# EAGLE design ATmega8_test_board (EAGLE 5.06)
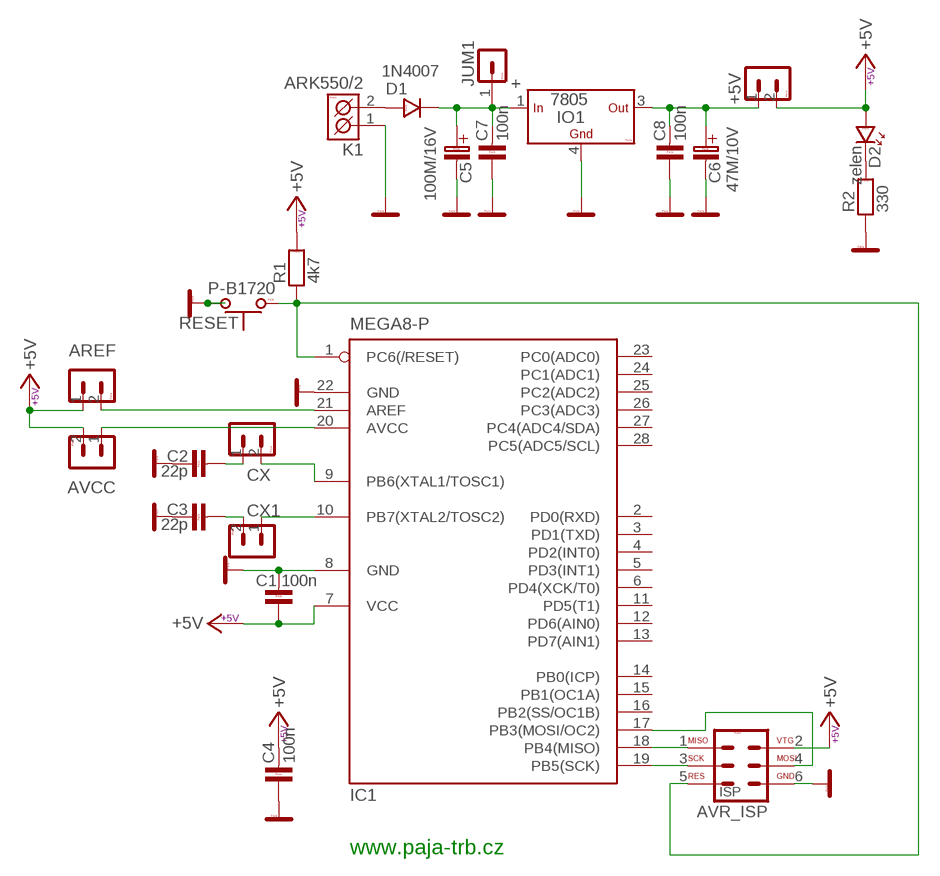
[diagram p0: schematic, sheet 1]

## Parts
+5V  S1G2_JUMP  [S1G2_JUM]
AREF  S1G2_JUMP  [S1G2_JUM]
AVCC  S1G2_JUMP  [S1G2_JUM]
C1  100n  C-KERAMIK_SMD_0805  [0805]
C2  22p  C-KERAMIK_SMD_0805  [0805]
C3  22p  C-KERAMIK_SMD_0805  [0805]
C4  100n  C-KERAMIK_SMD_1206  [1206]
C5  100M/16V  [C_EL_2,5]
C6  47M/10V  [C_EL_2]
C7  100n  C-KERAMIK_SMD_0805  [0805]
C8  100n  C-KERAMIK_SMD_0805  [0805]
CX  22p  S1G2_JUMP  [S1G2_JUM]
CX1  22p  S1G2_JUMP  [S1G2_JUM]
D1  1N4007  1N4007_SM-1  [SM-1]
D2  zelen  LED_SMD_1206  [P1206]
IC1  MEGA8-P  [DIL28-3]
IO1  7805  78D2PAKD2PAK  [D2PAK]
ISP  AVR_ISP  [MLW06G]
JUM1  +  S1G1_JUMP  [S1G1_JUM]
K1  ARK550/2  [ARK550/2]
R1  4k7  R_SMD_1206  [1206]
R2  330  R_SMD_1206  [1206]
RESET  P-B1720  [P-B1720]

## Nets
5V: +5V.1 C6.C+(C_EL+) C8.2 IO1.3(OUT)
+5V: +5V.2 AREF.1 AVCC.2 C1.1 C4.2 D2.A IC1.7(VCC) ISP.2 R1.2
GND: C1.2 C2.1 C3.1 C4.1 C5.C-(C_EL-) C6.C-(C_EL-) C7.1 C8.1 IC1.8(GND) IC1.22(GND) IO1.4(GND) ISP.6 K1.1(K1) R2.1 RESET.2 RESET.4(2A)
N$1: C5.C+(C_EL+) C7.2 D1.K IO1.1(IN) JUM1.1
N$2: CX.2 IC1.9(PB6(XTAL1/TOSC1))
N$3: C3.2 CX1.2
N$4: IC1.18(PB4(MISO)) ISP.1
N$5: IC1.19(PB5(SCK)) ISP.3
N$6: IC1.17(PB3(MOSI/OC2)) ISP.4
N$7: AREF.2 IC1.21(AREF)
N$8: AVCC.1 IC1.20(AVCC)
N$9: CX1.1 IC1.10(PB7(XTAL2/TOSC2))
N$10: C2.2 CX.1
N$11: D1.A K1.2(K2)
N$12: D2.K R2.2
RST: IC1.1(PC6(/RESET)) ISP.5 R1.1 RESET.1
Unconnected: IC1.2(PD0(RXD)) IC1.3(PD1(TXD)) IC1.4(PD2(INT0)) IC1.5(PD3(INT1)) IC1.6(PD4(XCK/T0)) IC1.11(PD5(T1)) IC1.12(PD6(AIN0)) IC1.13(PD7(AIN1)) IC1.14(PB0(ICP)) IC1.15(PB1(OC1A)) IC1.16(PB2(SS/OC1B)) IC1.23(PC0(ADC0)) IC1.24(PC1(ADC1)) IC1.25(PC2(ADC2)) IC1.26(PC3(ADC3)) IC1.27(PC4(ADC4/SDA)) IC1.28(PC5(ADC5/SCL)) RESET.3(1A)

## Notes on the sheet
- www.paja-trb.cz

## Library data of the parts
+5V AREF AVCC CX CX1 = #PaJa_konektory:S1G2_JUMP: Radove konektory - koliky - 2x
C1-C4 C7 C8 = #PaJa_31:C-KERAMIK: Kondenzator - keramicky
C5 = #PaJa_C-el_2:100M/16V
C6 = #PaJa_C-el_2:47M/10V
D1 = #PaJa_31:1N4007: Usmernovaci dioda - 1A, 1000V
D2 = #PaJa_31:LED: LED - jednobarevna
IC1 = atmel:MEGA8-P: MICROCONTROLLER 8 Kbytes FLASH, 1 kbytes SRAM, 512 bytes EEPROM, USART, 4-channel 10 bit ADC, 2-channel 8 bit ADC Pin compatible with Atmega48, ATMega88, ATMega168 Source: avr.lbr
IO1 = #PaJa_31:78??: Stabilizátor - 1A a 1,5A ?? - napeti => 05, 06, 08, 09, 12, 15, 18, 20, 24 => 1,5A ?? - napeti => 10, 12, 15, 18 => 1A S ?? - napeti => 05, 09, 10, 12, 15, 18, 24 => 2A T ?? - napeti => 05 => 3A
ISP = #PaJa_31:AVR_ISP: AVR ISP konektor (dle standardu)
JUM1 = #PaJa_konektory:S1G1_JUMP: Radove konektory - koliky - 1x
K1 = #PaJa_konektory:ARK550/2: Svorkovnice - roztec 3,5mm - dvojita
R1 R2 = #PaJa_31:R: Rezistor
RESET = #PaJa_prepinace:P-B1720: &micro;-tlacitko

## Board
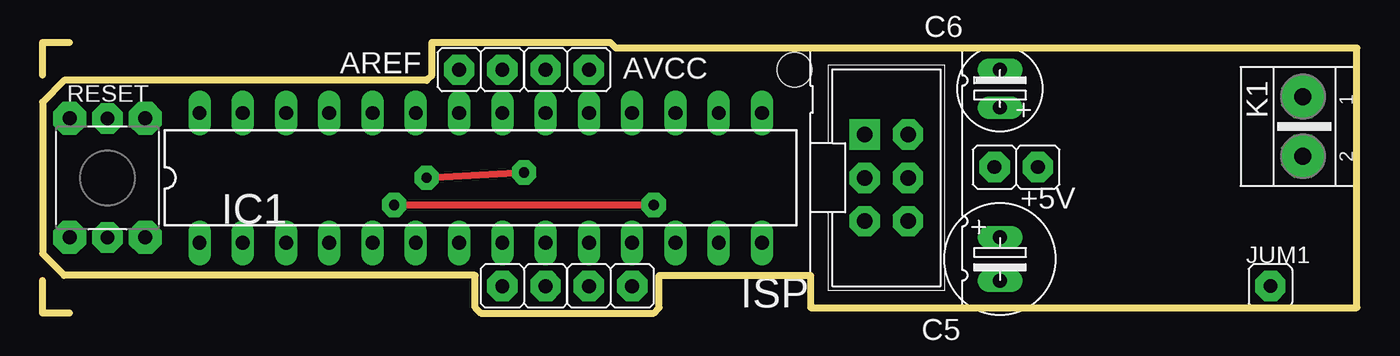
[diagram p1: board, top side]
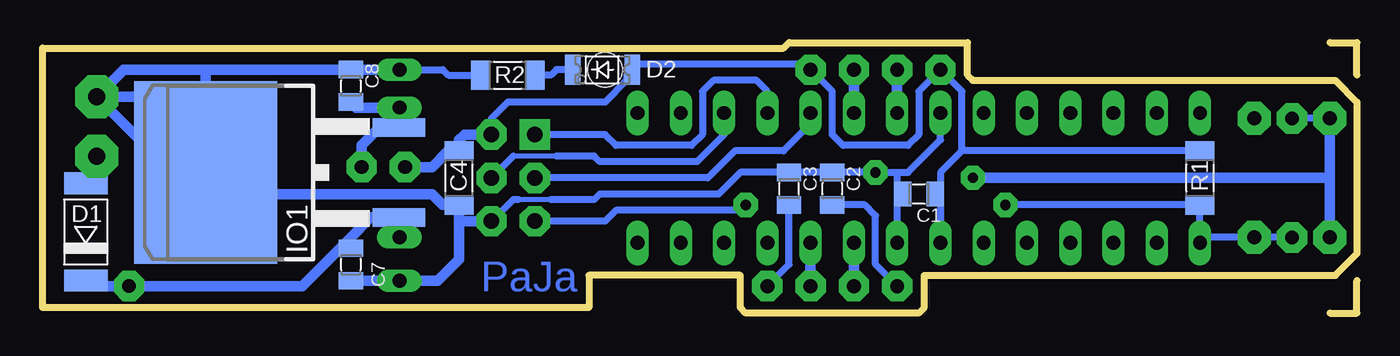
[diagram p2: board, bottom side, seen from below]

Size 77.15 x 15.88 mm. Coordinates in mm from the lower left corner, seen from the top.
Outline: 54.28,0.32 45.09,0.32 45.09,2.22 36.2,2.22 36.2,0.32 35.88,0 25.72,0 25.4,0.32 25.4,2.22 1.27,2.22 0,3.49 0,12.38 1.27,13.65 22.54,13.65 22.86,13.97 22.86,15.88 33.34,15.88 33.66,15.56 77.15,15.56 77.15,0.32 54.29,0.32
Outline: 1.59,0 0,0 0,1.91
Outline: 0,13.97 0,15.88 1.59,15.88
Copper layers (1*16): Top 0.035mm / dielectric 1.5mm / Bottom 0.035mm
Design rules "default": minimum track width 10mil, minimum drill 24mil, track to track 8mil, track to pad 8mil, pad to pad 8mil, via to via 8mil, smd to smd 8mil, copper to edge 40mil, drill to drill 8mil, minimum pad ring 10mil, minimum via ring 8mil, stop-mask expansion 4mil, vias tented up to drill 0mil, thermal gap 10mil
Holes 2 mm at 44.13,14.29

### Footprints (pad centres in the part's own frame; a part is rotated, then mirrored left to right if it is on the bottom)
S1G2_JUM = drill 0.813 pad 1.778 octagon: 1 -1.27,0; 2 1.27,0
0805 = smd 1.016 x 1.422: 1 -0.953,0; 2 0.953,0
1206 = smd 1.143 x 1.702: 1 -1.587,0; 2 1.587,0
C_EL_2,5 = drill 0.813 pad 1.27 long: C+ -1.27,0; C- 1.27,0
C_EL_2 = drill 0.813 pad 1.27 long: C+ 0,0; C- 2.223,0
SM-1 = smd 1.27 x 2.54: A 2.857,0; K -2.857,0
P1206 = smd 0.914 x 1.778: A -1.905,0; K 1.587,0
DIL28-3 = drill 0.813 long: 1 -16.51,-3.81; 2 -13.97,-3.81; 3 -11.43,-3.81; 4 -8.89,-3.81; 5 -6.35,-3.81; 6 -3.81,-3.81; 7 -1.27,-3.81; 8 1.27,-3.81; 9 3.81,-3.81; 10 6.35,-3.81; 11 8.89,-3.81; 12 11.43,-3.81; 13 13.97,-3.81; 14 16.51,-3.81; 15 16.51,3.81; 16 13.97,3.81; 17 11.43,3.81; 18 8.89,3.81; 19 6.35,3.81; 20 3.81,3.81; 21 1.27,3.81; 22 -1.27,3.81; 23 -3.81,3.81; 24 -6.35,3.81; 25 -8.89,3.81; 26 -11.43,3.81; 27 -13.97,3.81; 28 -16.51,3.81
D2PAK = smd 1.1 x 3.1: 1 -2.641,-8.535; 3 2.641,-8.535 | smd 10.7 x 8.4: 4 0,2.817
MLW06G = drill 0.914 pad 1.778 square: 1 -2.54,-1.27 | drill 0.914 pad 1.778 octagon: 2 -2.54,1.27; 3 0,-1.27; 4 0,1.27; 5 2.54,-1.27; 6 2.54,1.27
S1G1_JUM = drill 0.8 pad 1.778 octagon: 1 0,0
ARK550/2 = drill 1.016 pad 2.54 octagon: 1 0,0; 2 3.493,0
P-B1720 = drill 0.813 pad 1.93 octagon: 1 -3.493,-2.223; 2 -3.493,2.223; 3 3.493,-2.223; 4 3.493,2.223

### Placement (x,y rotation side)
+5V  57.15,8.57 180 top
AREF  25.72,14.29 0 top
AVCC  30.8,14.29 0 top
C1  25.72,6.99 180 bottom
C2  30.8,7.3 270 bottom
C3  33.34,7.3 270 bottom
C4  52.7,7.94 90 bottom
C5  56.2,3.17 270 top
C6  56.2,12.06 90 top
C7  59.05,2.86 90 bottom
C8  59.05,13.34 270 bottom
CX  28.26,1.59 0 top
CX1  33.34,1.59 0 top
D1  74.61,4.76 90 bottom
D2  44.45,14.29 180 bottom
IC1  25.72,7.94 0 top
IO1  64.77,8.26 90 bottom
ISP  49.53,7.94 270 top
JUM1  72.07,1.59 0 top
K1  73.98,12.7 270 top
R1  9.21,7.94 90 bottom
R2  49.85,13.97 0 bottom
RESET  3.81,7.94 90 top

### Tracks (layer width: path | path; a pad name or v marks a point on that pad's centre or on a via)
5V
  Bottom 0.406: IO1.3 56.2,10.93 | 58.74,12.06 C8.2
  Bottom 0.61: 56.2,10.93 C6.C+ 58.74,12.06 | IO1.3 57.37,10.9 58.42,9.84 +5V.1
+5V
  Bottom 0.406: ISP.2 50.8,11.43 49.85,12.38 44.13,12.38 42.86,13.65 42.86,13.97 D2.A 42.23,14.61 | 24.45,6.99 IC1.7 | R1.2 23.18,9.53 | 23.18,9.53 23.18,13.02 AREF.1 25.72,13.02 25.72,10.48 26.35,9.84 30.16,9.84 30.8,10.48 30.8,13.02 AVCC.2 32.38,14.61 42.23,14.61 | 23.18,9.53 24.45,8.26 24.45,6.99 | 24.45,6.99 C1.1 | C4.2 53.34,9.53 | 42.23,14.61
  Bottom 0.61: ISP.2 52.39,10.48 52.7,10.16 C4.2 | +5V.2 54.29,8.57 53.34,9.53
GND  (via drill 0.6 pad 1.42, 0.8 pad 1.78)
  Top 0.406: v22.54,7.94 v28.26,8.26
  Bottom 0.305: 47.31,6.67 49.21,6.67
  Bottom 0.406: ISP.6 49.53,6.67 49.21,6.67 | 26.99,6.99 IC1.8 | 26.99,6.99 C1.2 | 26.99,8.26 26.99,6.99 | 26.99,8.26 v28.26,8.26 C2.1 C3.1 36.2,8.26 37.47,6.99 44.45,6.99 44.77,6.67 47.31,6.67 | RESET.4 v3.81,11.43 | 26.99,8.26 26.35,8.26 24.45,10.16 IC1.22 | 67.59,14.25 67.63,14.29 | 67.63,6.99 67.59,7.03 IO1.4 | R2.1 53.34,13.97 53.66,14.29 C6.C-
  Bottom 0.61: RESET.2 1.59,7.94 | ISP.6 52.7,5.4 | 52.7,5.4 C4.1 53.66,6.35 54.29,6.99 67.63,6.99 | 1.59,7.94 v22.54,7.94 | 1.59,7.94 RESET.4 | C7.1 C5.C- 53.98,1.91 52.7,3.17 52.7,5.4 | C6.C- C8.1 67.63,14.29 72.39,14.29 K1.1 | IO1.4 67.59,14.25 | K1.1 71.12,9.84 | K1.1 70.8,12.7
N$1
  Bottom 0.406: 56.2,5.58 IO1.1 | 59.05,4.45 C7.2 | 73.66,1.59 D1.K
  Bottom 0.61: IO1.1 57.89,5.61 59.05,4.45 61.91,1.59 JUM1.1 73.66,1.59 | C5.C+ 56.2,5.58
N$2
  Bottom 0.61: CX.2 IC1.9
N$3
  Bottom 0.406: C3.2 33.34,2.86 CX1.2
N$4
  Bottom 0.406: IC1.18 34.61,13.02 35.24,13.65 37.78,13.65 38.42,13.02 38.42,10.48 39.05,9.84 43.5,9.84 44.13,10.48 ISP.1
N$5
  Bottom 0.406: ISP.3 38.1,7.94 36.51,9.53 33.66,9.53 32.07,11.11 IC1.19
N$6
  Bottom 0.305: 46.99,9.21 49.53,9.21
  Bottom 0.406: IC1.17 37.15,10.48 38.73,8.89 44.45,8.89 44.77,9.21 46.99,9.21 | 49.53,9.21 ISP.4
N$7
  Bottom 0.61: IC1.21 AREF.2
N$8
  Bottom 0.61: IC1.20 AVCC.1
N$9
  Bottom 0.61: CX1.1 IC1.10
N$10
  Bottom 0.406: CX.1 28.26,2.86 28.26,5.71 28.89,6.35 C2.2
N$11
  Bottom 0.61: D1.A K1.2
N$12
  Bottom 0.406: D2.K 46.99,14.29 47.31,13.97 R2.2
RST  (via drill 0.6 pad 1.42, 0.8 pad 1.78)
  Top 0.406: v20.64,6.35 v35.88,6.35
  Bottom 0.406: 9.21,4.45 RESET.1 v3.81,4.45 | 44.13,5.4 46.67,5.4 | 44.13,5.4 ISP.5 | 9.21,4.45 IC1.1 | 9.21,4.45 R1.1 v20.64,6.35 | 44.13,5.4 43.5,6.03 36.2,6.03 v35.88,6.35

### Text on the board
Bottom: PaJa
PaJa: www.paja-trb.cz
